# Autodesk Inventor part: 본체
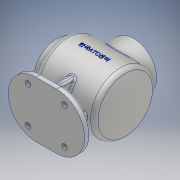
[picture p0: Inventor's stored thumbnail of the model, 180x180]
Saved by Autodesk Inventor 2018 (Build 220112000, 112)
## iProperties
Created: 2023-01
Part Number: 본체
Material: 알루미늄 6061
Document SubType Name: Modeling
Designer: home
Density: 2.7 g/cm^3
Appearance: 알루미늄 - 평지
Author: home
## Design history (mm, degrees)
sketch "스케치1"
  geometry: L1 (17, 0)-(-17, 0); L2 (17, -46)-(-17, -46); L3 (17, 46)-(-17, 46); A1 r 46 centre (-17, 0) between (-17, 46) and (-17, -46); A2 r 46 centre (17, 0) between (17, -46) and (17, 46); 1 further point
  constraints: 6 end point, 4 point on circle, 3 horizontal, 2 centre point, 2 coincident, 2 tangent, 1 midpoint
  dimensions: "d0" = 34 distance of L1.start L1.end; "d1" = 17 distance of point (0, 0) L1.start (= 0.5 x d0); "d3" = 92 diameter of A1; "d4" = 46 radius of A2
extrude "돌출1" new body sketch "스케치1" distance "d5" = 10; taper "d6" = 0 deg
sketch "스케치2"
  geometry: L1 (-30, 30)-(30, 30); L2 (30, 30)-(30, -30); L3 (30, -30)-(-30, -30); L4 (-30, -30)-(-30, 30); L5 (-30, 30)-(30, -30); L6 (30, 30)-(-30, -30); 5 further points
  constraints: 12 end point, 4 coincident, 2 midpoint, 2 parallel, 1 horizontal, 1 perpendicular
  dimensions: "d7" = 60 distance of L2.end L3.end; "d8" = 60 distance of L1.end L2.end
hole "구멍1" sketch "스케치2" at (-30, 30), (-30, -30), (30, -30), (30, 30) diameter "d9" = 9; stored, may be unused: countersink angle "d13" = 90 deg, drill point angle "d15" = 118 deg; dims "d10" = 6, "d11" = 4, "d12" = 2, "d14" = 8
sketch "스케치3"
  geometry: L1 (-85.249, 80)-(98.9, 80); L2 (17, 0)-(-17, 0) reference; L3 (-51, 80)-(-51, 130); L4 (-51, 130)-(48.087, 130); L5 (59, 130)-(59, 80); L6 (-63, 0)-(-17, 0) reference; L7 (-63, 0)-(-63, 145.307); L8 (-46, 80)-(-46, 125); L9 (-46, 125)-(44.83, 125); L10 (54, 125)-(54, 80); L11 (-51, 118)-(-63, 118); L12 (-63, 118)-(-63, 107); L13 (-63, 107)-(-46, 107); L14 (-51, 130)-(-51, 118); L15 (-46, 107)-(-46, 125); L16 (54, 80)-(59, 80); A1 r 120 centre (-61, 80) between (59, 80) and (48.087, 130); A2 r 115 centre (-61, 80) between (54, 80) and (44.83, 125); 1 further point
  constraints: 28 end point, 10 point on line, 7 perpendicular, 4 point on circle, 2 centre point, 2 collinear, 2 tangent, 2 vertical, 1 horizontal, 1 parallel
  dimensions: "d16" = 80 distance between parallel lines of L2 L1; "d17" = 100 diameter of L4 L1; "d18" = 12 distance between parallel lines of L3 L7; "d19" = 110 distance between parallel lines of L5 L3; "d20" = 240 diameter of A1; "d21" = 5 distance between parallel lines of L5 L10; "d22" = 5 distance between parallel lines of L4 L9; "d23" = 5 distance between parallel lines of L3 L8; "d24" = 230 diameter of A2; "d25" = 76 diameter of L11 L1; "d26" = 54 diameter of L13 L1; "d27" = 17 distance between parallel lines of L15 L12 (derived); "d83" = 130 distance from line of L5.start L2; "d84" = 125 distance from line of L10.start L2; "d85" = 145.30657 distance from line of L7.end L2; "d86" = 39.90029 distance from line of L1.end L5; "d87" = 144.24868 distance from line of L1.start L5
revolve "회전1" sketch "스케치3" stored, may be unused: angle "d28" = 90 deg
sketch "스케치4"
  geometry: L1 (-17, 10)-(-63, 10) reference; L2 (-51, 30)-(48.087, 30) reference; L3 (-34.5, 0)-(-34.5, 10) reference; L4 (44.83, 35)-(-46, 35) reference; L5 (-40, 10)-(40, 10); L6 (-40, 10)-(-33.971, 32.5); L7 (40, 10)-(33.971, 32.5); L8 (63, 10)-(17, 10) reference; L9 (-33.971, 32.5)-(33.971, 32.5); L10 (-63, 0)-(-63, 10) reference; 1 further point
  constraints: 8 end point, 2 horizontal, 1 midpoint
  dimensions: "d34" = 80 distance of L5.start L5.end; "d35" = 40 horizontal distance of point (0, 0) L5.start (= 0.5 x d34); "d36" = 105 deg angle of L1 L6; "d37" = 105 deg angle of L8 L7; "d38" = 2.5 distance between parallel lines of L2 L9
extrude "돌출2" join sketch "스케치4" stored distance "d39" = 10; taper "d40" = 0 deg
sketch "스케치5"
  geometry: L1 (10, -46)-(10, 46) reference; L2 (10, -35)-(44.293, -35); L3 (44.293, 35)-(10, 35); L4 (10, 35)-(10, -35); A1 r 50 centre (80, 0) between (44.293, -35) and (44.293, 35) reference; 1 further point
  constraints: 6 end point, 2 point on circle, 1 collinear, 1 horizontal, 1 parallel, 1 point on line
  dimensions: "d41" = 70 distance between parallel lines of L3 L2; "d42" = 35 distance from line of point (0, 0) L2 (= 0.5 x d41)
extrude "돌출3" join sketch "스케치5" stored distance "d43" = 10; taper "d44" = 0 deg
node "작업 평면1"
sketch "스케치6"
  geometry: C1 r 38 at (0, 0); 1 further point
  constraints: 1 centre point, 1 coincident
  dimensions: "d46" = 76 diameter of C1
extrude "돌출4" join sketch "스케치6" stored distance "d47" = 10; taper "d48" = 0 deg
sketch "스케치7"
  geometry: L1 (0, 32.5)-(0, -32.5); L2 (-32.5, 0)-(32.5, 0); C1 r 38 at (0, 0) reference; A1 r 32.5 centre (0, 0) between (0, 32.5) and (0, -32.5); 7 further points
  constraints: 5 coincident, 4 end point, 4 midpoint, 4 point on circle, 1 centre point, 1 perpendicular, 1 vertical
  dimensions: "d49" = 65 diameter of A1
hole "구멍2" sketch "스케치7" at (0, 32.5), (-32.5, 0), (0, -32.5), (32.5, 0) diameter "d50" = 3.242; stored, may be unused: countersink angle "d54" = 90 deg, drill point angle "d56" = 118 deg; dims "d51" = 8, "d52" = 4, "d53" = 2, "d55" = 10
sketch "스케치8"
  geometry: 2 further points
  constraints: 1 coincident
hole "구멍3" sketch "스케치8" at (0, 0) diameter "d57" = 54; stored, may be unused: countersink angle "d61" = 90 deg, drill point angle "d63" = 118 deg; dims "d58" = 8, "d59" = 4, "d60" = 2, "d62" = 10
sketch "스케치9"
  geometry: L1 (0, 32.5)-(0, -32.5); L2 (-32.5, 0)-(32.5, 0); A1 r 32.5 centre (0, 0) between (0, 32.5) and (0, -32.5); 10 further points; 1 other entity
  constraints: 5 coincident, 4 end point, 4 point on circle, 3 midpoint, 1 centre point, 1 horizontal, 1 vertical, 1 other
  dimensions: "d64" = 65 diameter of A1; "d88" = 0 distance from line of point (0, 0) L2; "d89" = 0 distance from line of point (0, 0) L1
hole "구멍4" sketch "스케치9" at (-32.5, 0), (0, 32.5), (0, -32.5), (32.5, 0) diameter "d65" = 3.242; stored, may be unused: countersink angle "d69" = 90 deg, drill point angle "d71" = 118 deg; dims "d66" = 8, "d67" = 4, "d68" = 2, "d70" = 10
node "작업 평면2"
sketch "스케치10"
  geometry: L1 (17, 0)-(63, 0) reference; L2 (0, 0)-(0, 177.758); L3 (-63, 42)-(-63, 118) reference; L4 (-63, 80)-(59, 80); A1 r 120 centre (-61, 80) between (48.087, 30) and (48.087, 130) reference
  constraints: 4 end point, 2 horizontal, 1 midpoint, 1 point on circle, 1 vertical
  dimensions: "d74" = 63 distance between parallel lines of L3 L2 (derived); "d75" = 80 distance between parallel lines of L1 L4; "d90" = 177.75788 distance from line of L2.end L1
feature "엠보싱1" sketch "스케치10" dims "d0" = 34, "d1" = 17 (= 0.5 x d0), "d3" = 92, "d4" = 46, "d76" = 0.5, "d77" = 0
chamfer "모따기1" distance "d78" = 1; stored, may be unused: second distance "d79" = 2, angle "d80" = 45 deg
fillet "모깎기1" dims "d81" = 3, "d82" = 8
node "솔리드1"
other parameters: "d2" = 92, "d45" = -144
